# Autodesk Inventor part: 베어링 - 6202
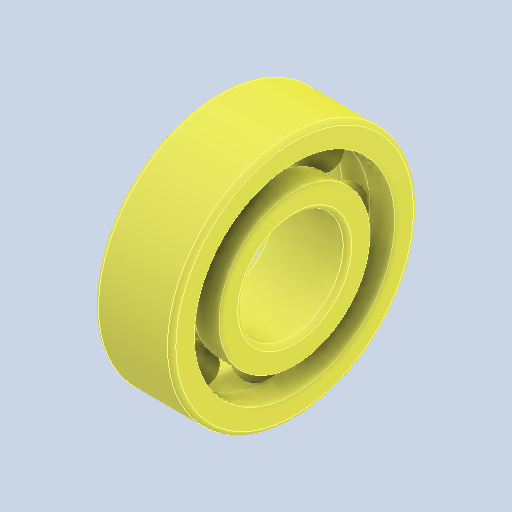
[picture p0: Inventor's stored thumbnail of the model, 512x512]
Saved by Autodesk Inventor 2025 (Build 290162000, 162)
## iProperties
Created: 2025-08
Part Number: 베어링 - 6202
Material: 강, 연강
Description: 깊은 그루브 볼 베어링
Document SubType Name: Modeling
Designer: infra02
Density: 7.86 g/cm^3
Appearance: 기본값
Author: jhkim
Sending System: Autodesk Inventor 2026
Preprocessor: ST-DEVELOPER v20.1
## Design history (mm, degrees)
feature "Solid1"
feature "Solid1:1"
feature "Solid1:2"
feature "Solid1:3"
feature "Solid1:4"
feature "Solid1:5"
feature "Solid1:6"
feature "Solid1:7"
feature "Solid1:8"
feature "Solid1:9"
node "솔리드1"
node "솔리드2"
node "솔리드3"
node "솔리드4"
node "솔리드5"
node "솔리드6"
node "솔리드7"
node "솔리드8"
node "솔리드9"
node "솔리드10"
